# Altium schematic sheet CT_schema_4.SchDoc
size 388 x 258 mm
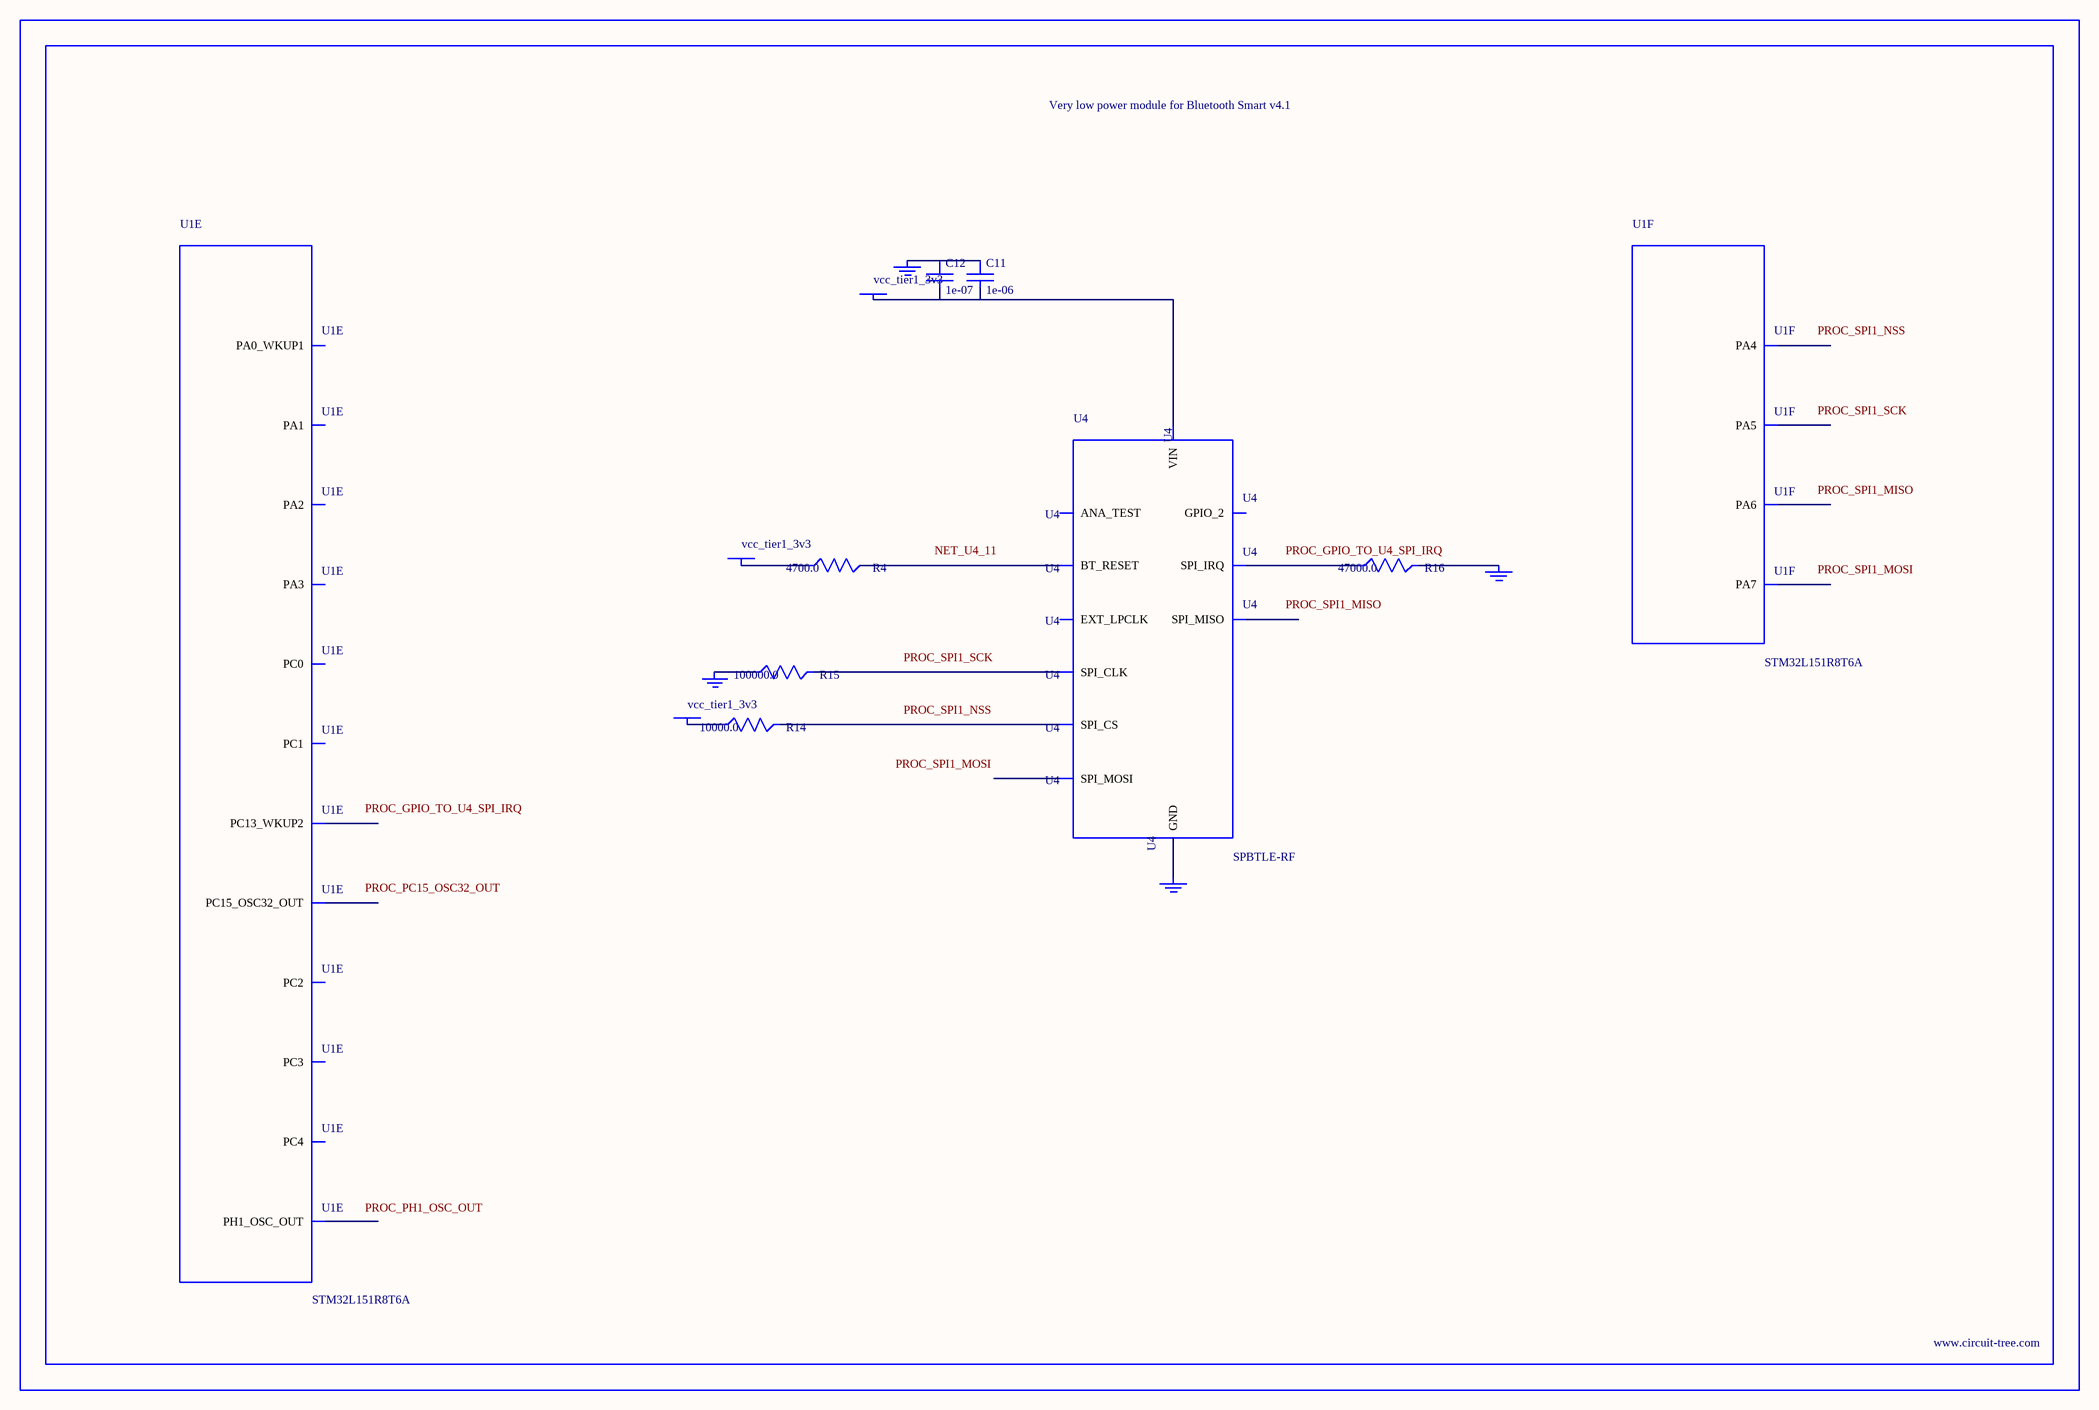
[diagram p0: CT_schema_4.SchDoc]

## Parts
BORDER3  (no value)
C11  1e-06  [C0603]
C12  1e-07  [C0402]
GND_INSTANCE_3_0  (no value)
GND_INSTANCE_3_1  (no value)
GND_INSTANCE_3_2  (no value)
GND_INSTANCE_3_3  (no value)
POWER_INSTANCE_3_0  vcc_tier1_3v3
POWER_INSTANCE_3_1  vcc_tier1_3v3
POWER_INSTANCE_3_2  vcc_tier1_3v3
R4  4700.0  [R0603]
R14  10000.0  [R0603]
R15  100000.0  [R0603]
R16  47000.0  [R0603]
U1  STM32L151R8T6A  [LQFP64]  (parts E,F of 7)
U4  SPBTLE-RF  [XCVR_SPBTLE-RF]

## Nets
NetC11_1: C11.1 C12.1 GND_INSTANCE_3_1.0(GND)
NetC11_2: C11.2 C12.2 POWER_INSTANCE_3_0.0(PWR) U4.5(VIN)
NetGND_INSTANCE_3_0_0: GND_INSTANCE_3_0.0(GND) R16.2
NetGND_INSTANCE_3_2_0: GND_INSTANCE_3_2.0(GND) R15.1
NetGND_INSTANCE_3_3_0: GND_INSTANCE_3_3.0(GND) U4.6(GND)
NetPOWER_INSTANCE_3_1_0: POWER_INSTANCE_3_1.0(PWR) R14.1
NetPOWER_INSTANCE_3_2_0: POWER_INSTANCE_3_2.0(PWR) R4.1
NetR4_2: R4.2 U4.11(BT_RESET)
NetR14_2: R14.2 U4.10(SPI_CS)
NetR15_2: R15.2 U4.7(SPI_CLK)
NetR16_1: R16.1 U4.4(SPI_IRQ)

Not connected (* = marked no-connect by the designer): U1 2(PC13_WKUP2) 4(PC15_OSC32_OUT) 6(PH1_OSC_OUT) 8(PC0) 9(PC1) 10(PC2) 11(PC3) 14(PA0_WKUP1) 15(PA1) 16(PA2) 17(PA3) 20(PA4) 21(PA5) 22(PA6) 23(PA7) 24(PC4); U4 1(EXT_LPCLK) 2(GPIO_2) 3(ANA_TEST) 8(SPI_MISO) 9(SPI_MOSI)

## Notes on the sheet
- Labels drawn without touching a wire or pin: NET_U4_11, PROC_GPIO_TO_U4_SPI_IRQ, PROC_PC15_OSC32_OUT, PROC_PH1_OSC_OUT, PROC_SPI1_MISO, PROC_SPI1_MOSI, PROC_SPI1_NSS, PROC_SPI1_SCK

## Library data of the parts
BORDER3 = BORDER_PAGE3
C11 = C0603C105K3RACTU
C12 = C0402C104K3RACTU
GND_INSTANCE_3_0-GND_INSTANCE_3_3 = GND
POWER_INSTANCE_3_0-POWER_INSTANCE_3_2 = PWR
R4 = RC0603JR-074K7L
R14 = RC0603JR-0710KL
R15 = RC0603JR-07100KL
R16 = RC0603JR-0747KL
